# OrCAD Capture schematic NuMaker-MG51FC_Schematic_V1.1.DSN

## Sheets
1 Nu-Link2-Me: size A3; title: Nu-Link2-Me; rev: 1.0; company: CMHuang; note: Nu-Link2-Me
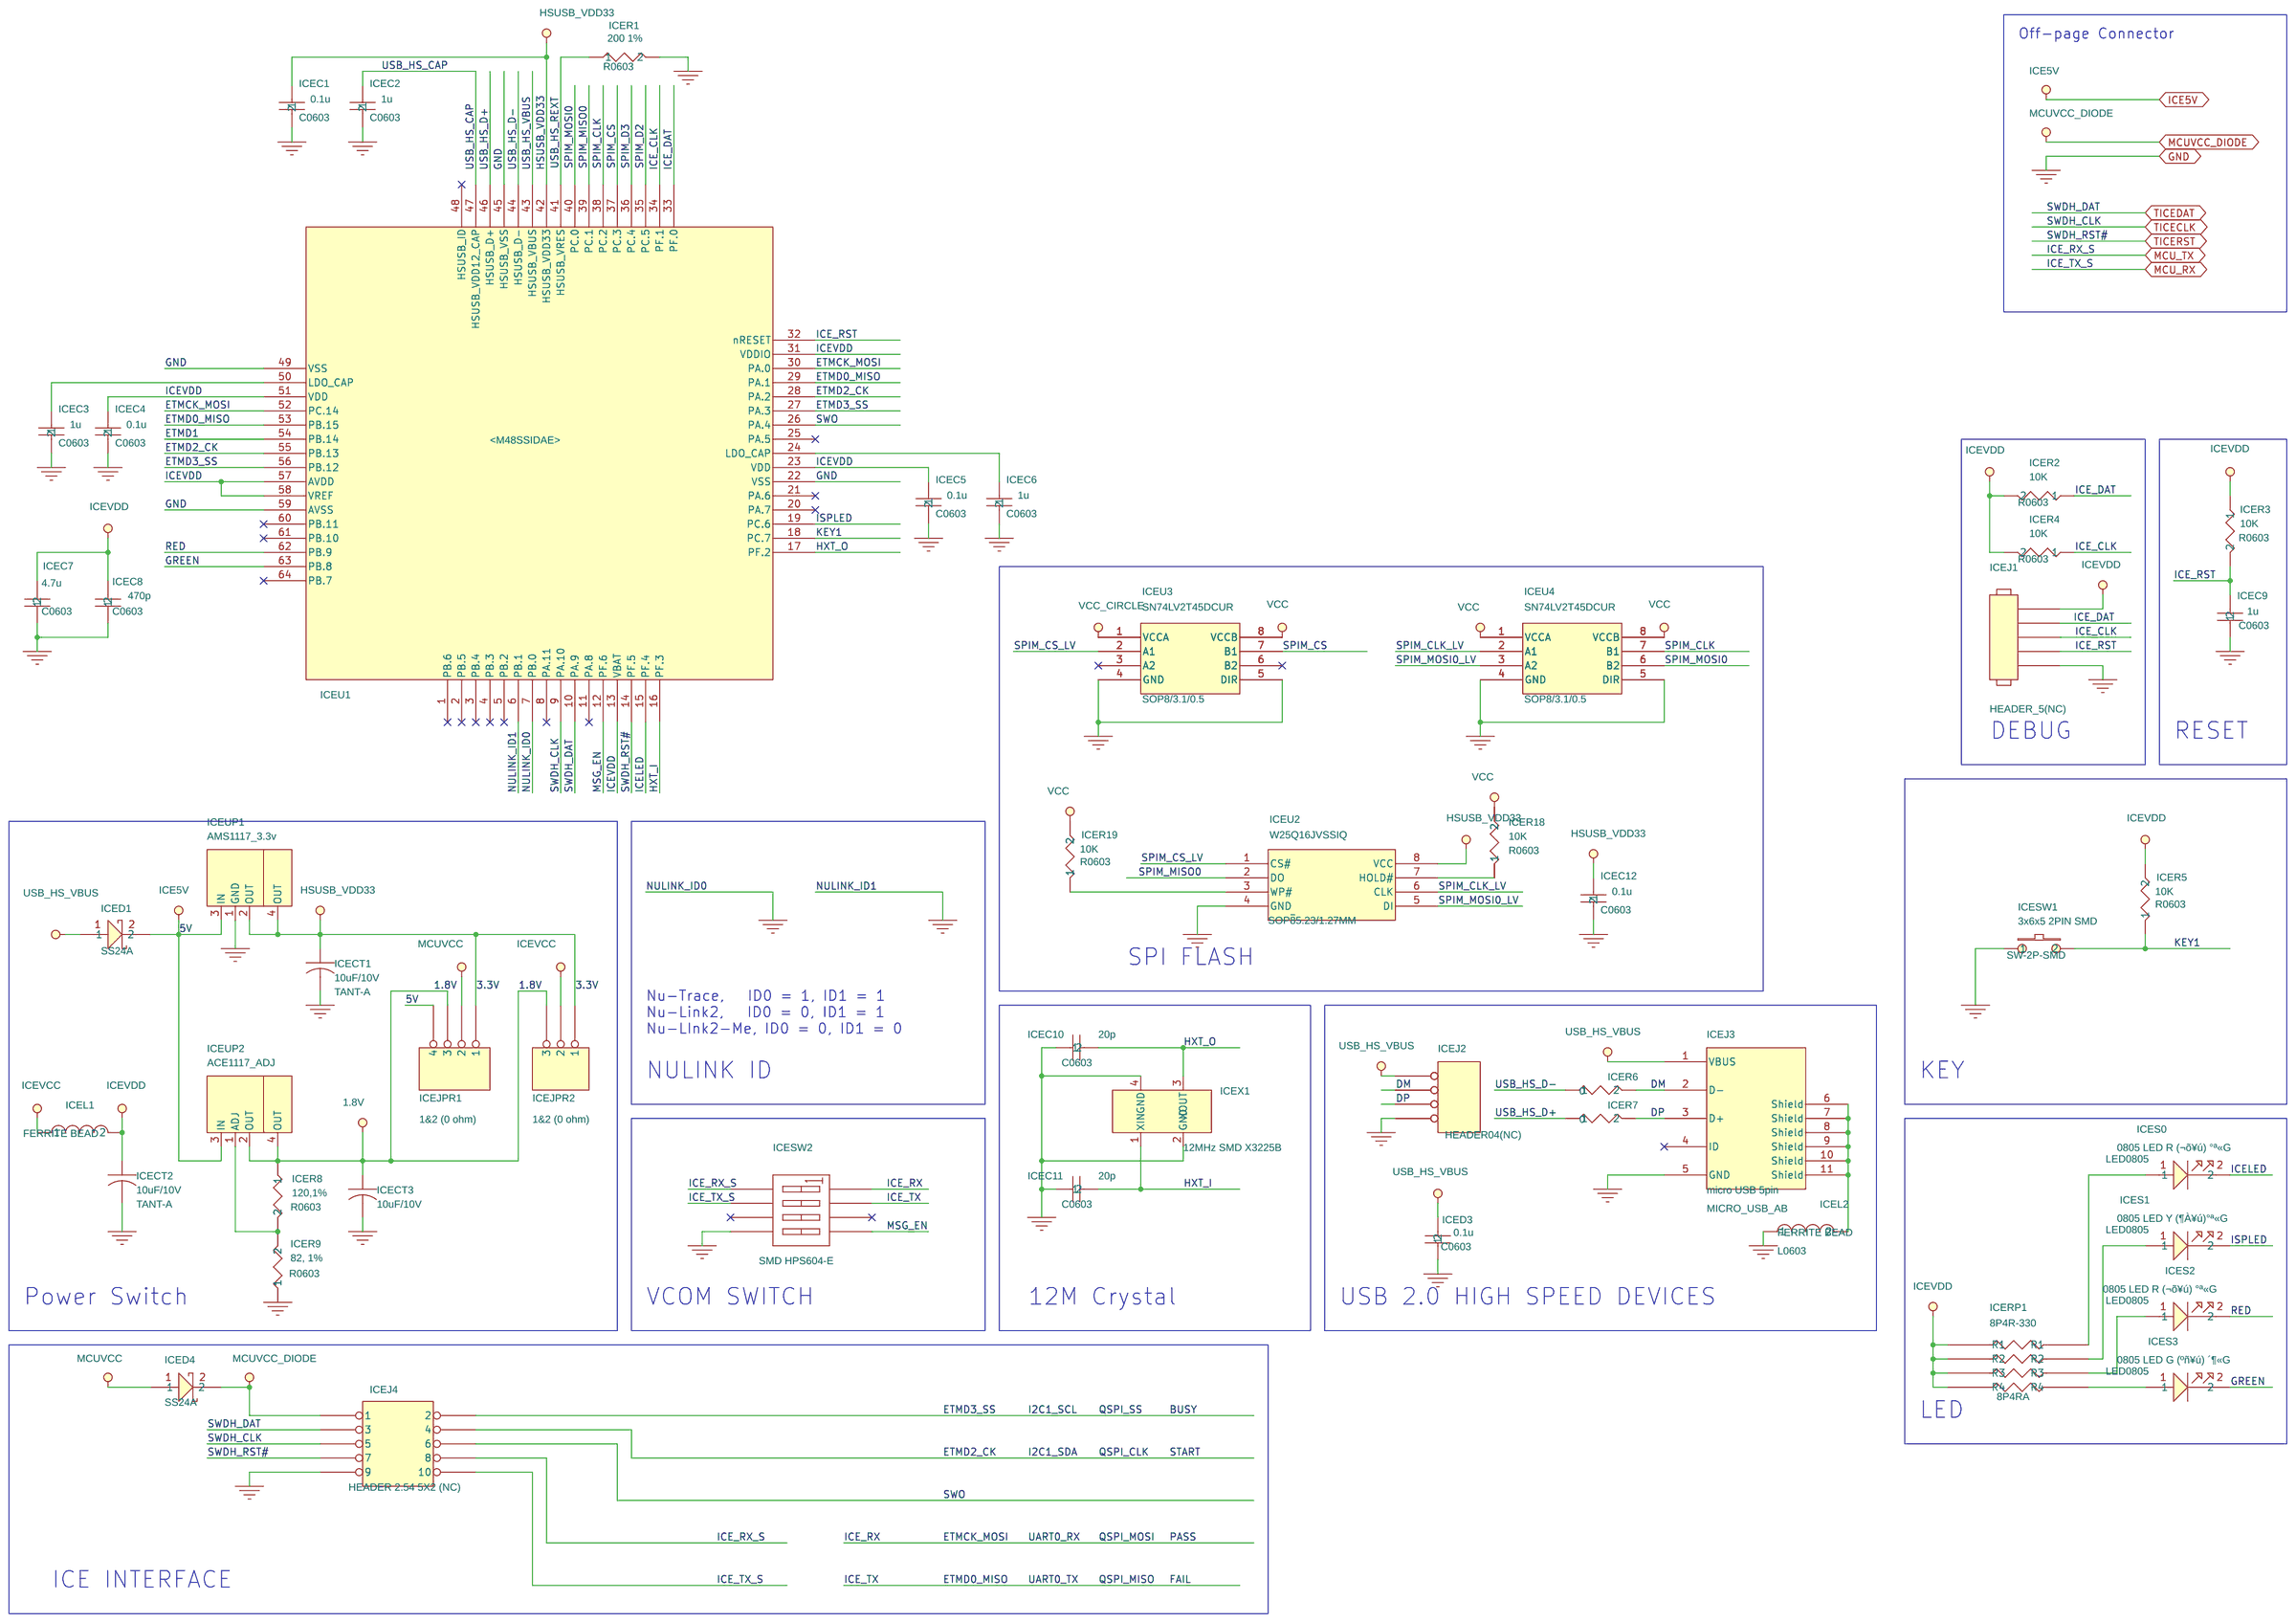
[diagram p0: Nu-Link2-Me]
2 MG51FC9AE: size Custom; title: MS51PC0AE; rev: v1.1; note: NuMaker-MS51PC
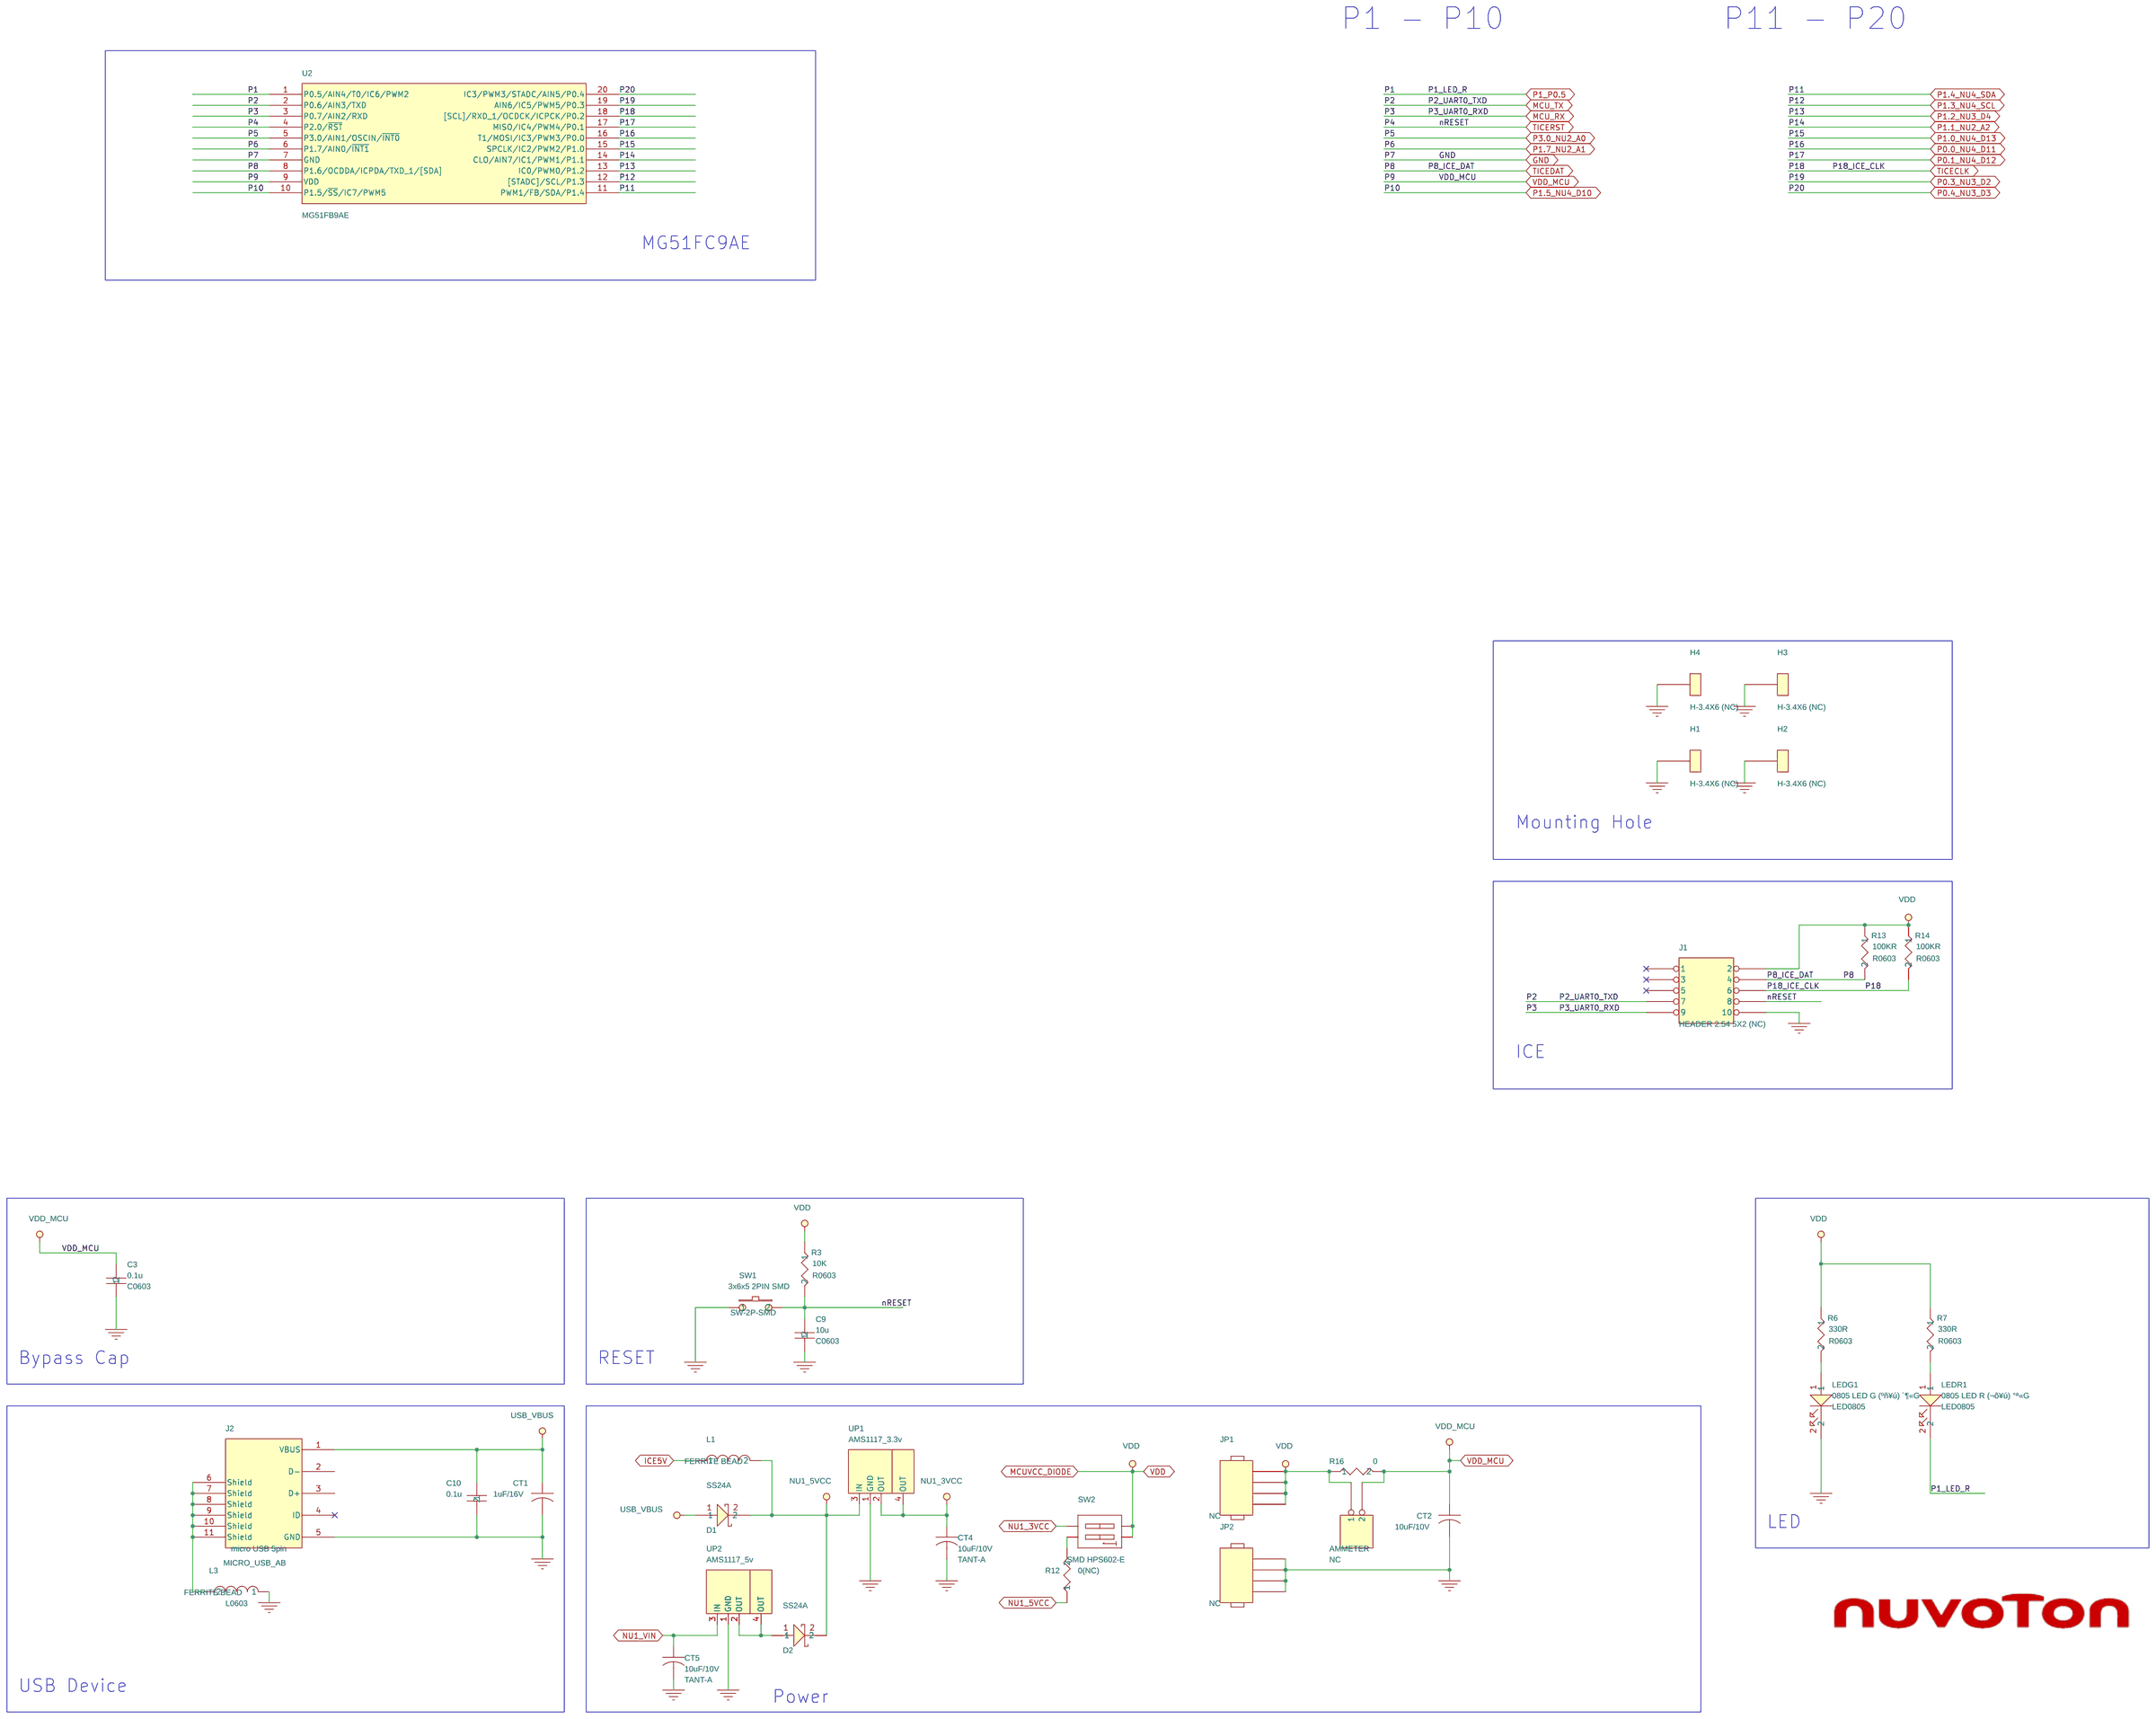
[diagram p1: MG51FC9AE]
3 Ext. Connector: size Custom; title: Ext. Connector; rev: v1.1; note: NuMaker-MS51PC
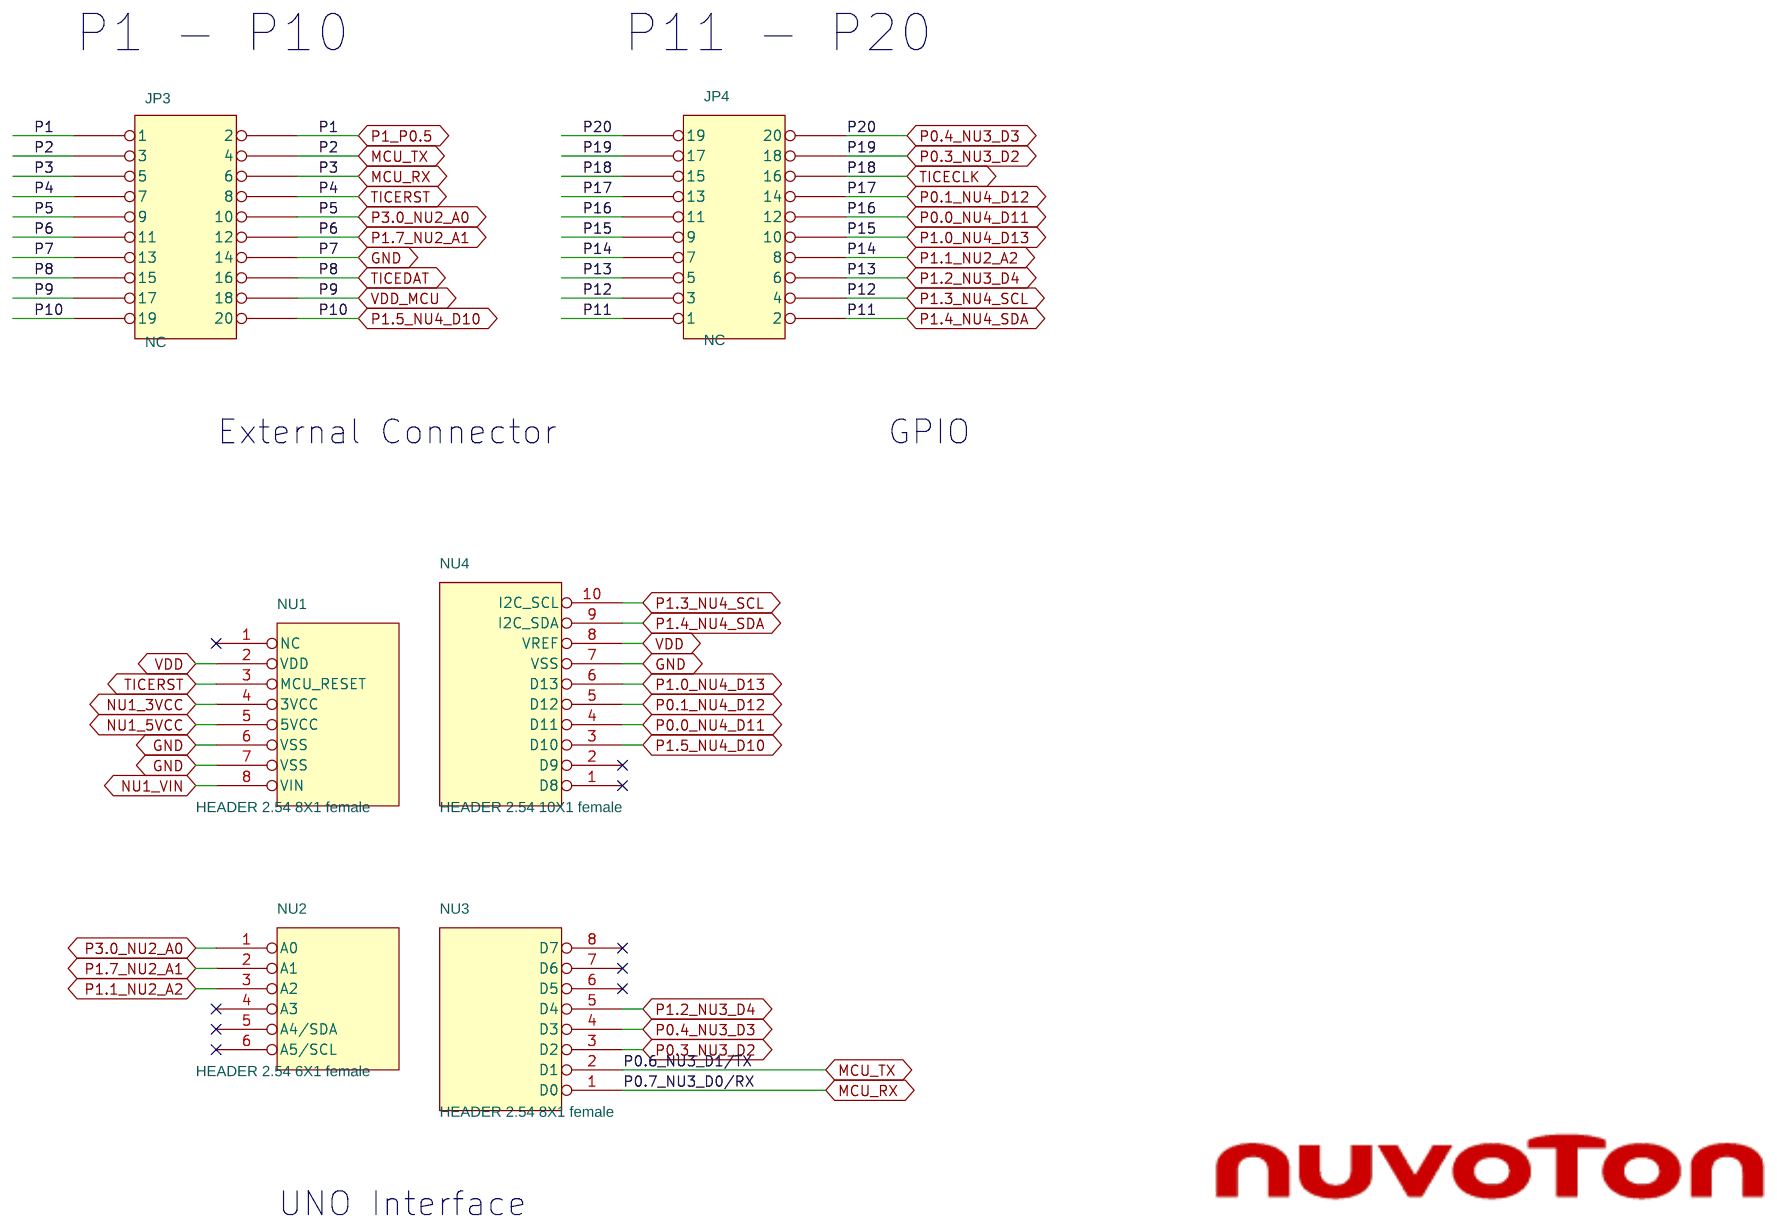
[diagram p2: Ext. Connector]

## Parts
sheet Ext. Connector
JP3  NC  [header10x2]
JP4  NC  [header10x2]
NU1  HEADER 2.54 8X1 female  [SIP-8P]
NU2  HEADER 2.54 6X1 female  [SIP-6P]
NU3  HEADER 2.54 8X1 female  [SIP-8P]
NU4  HEADER 2.54 10X1 female  [SIP-10P]
sheet MG51FC9AE
AMMETER  NC  [HEADER2X1]
C3  0.1u  [C0603]
C9  10u  [C0603]
C10  0.1u  [C0603]
CT1  1uF/16V  [TANT-A]
CT2  10uF/10V  [TANT-A]
CT4  10uF/10V  [TANT-A]
CT5  10uF/10V  [TANT-A]
D1  SS24A  [RB060L]
D2  SS24A  [RB060L]
H1  H-3.4X6 (NC)  [H-3.4X6]
H2  H-3.4X6 (NC)  [H-3.4X6]
H3  H-3.4X6 (NC)  [H-3.4X6]
H4  H-3.4X6 (NC)  [H-3.4X6]
J1  HEADER 2.54 5X2 (NC)  [HEADER5X2]
J2  micro USB 5pin  [MICRO_USB_AB]
JP1  NC  [header1x4]
JP2  NC  [header1x4]
L1  FERRITE BEAD  [L0603]
L3  FERRITE BEAD  [L0603]
LEDG1  0805 LED G (ºñ¥ú) ´¶«G  [LED0805]
LEDR1  0805 LED R (¬õ¥ú) °ª«G  [LED0805]
R3  10K  [R0603]
R6  330R  [R0603]
R7  330R  [R0603]
R12  0(NC)  [R0603]
R13  100KR  [R0603]
R14  100KR  [R0603]
R16  0  [R0603]
SW1  3x6x5 2PIN SMD  [SW-2P-SMD]
SW2  SMD HPS602-E  [SW1X2]
U2  MG51FB9AE  [TSSOP20]
UP1  AMS1117_3.3v  [SOT-223-1]
UP2  AMS1117_5v  [SOT-223-1]
sheet Nu-Link2-Me
ICEC1  0.1u  [C0603]
ICEC2  1u  [C0603]
ICEC3  1u  [C0603]
ICEC4  0.1u  [C0603]
ICEC5  0.1u  [C0603]
ICEC6  1u  [C0603]
ICEC7  4.7u  [C0603]
ICEC8  470p  [C0603]
ICEC9  1u  [C0603]
ICEC10  20p  [C0603]
ICEC11  20p  [C0603]
ICEC12  0.1u  [C0603]
ICECT1  10uF/10V  [TANT-A]
ICECT2  10uF/10V  [TANT-A]
ICECT3  10uF/10V  [TANT-A]
ICED1  SS24A  [RB060L]
ICED3  0.1u  [C0603]
ICED4  SS24A  [RB060L]
ICEJ1  HEADER_5(NC)  [HEADER5X1]
ICEJ2  HEADER04(NC)  [HEADER04]
ICEJ3  micro USB 5pin  [MICRO_USB_AB]
ICEJ4  HEADER 2.54 5X2 (NC)  [HEADER5X2]
ICEJPR1  1&2 (0 ohm)  [R0603X3]
ICEJPR2  1&2 (0 ohm)  [R0603X2]
ICEL1  FERRITE BEAD  [L0603]
ICEL2  FERRITE BEAD  [L0603]
ICER1  200 1%  [R0603]
ICER2  10K  [R0603]
ICER3  10K  [R0603]
ICER4  10K  [R0603]
ICER5  10K  [R0603]
ICER6  0  [R0603]
ICER7  0  [R0603]
ICER8  120,1%  [R0603]
ICER9  82, 1%  [R0603]
ICER18  10K  [R0603]
ICER19  10K  [R0603]
ICERP1  8P4R-330  [8P4RA]
ICES0  0805 LED R (¬õ¥ú) °ª«G  [LED0805]
ICES1  0805 LED Y (¶À¥ú)°ª«G  [LED0805]
ICES2  0805 LED R (¬õ¥ú) °ª«G  [LED0805]
ICES3  0805 LED G (ºñ¥ú) ´¶«G  [LED0805]
ICESW1  3x6x5 2PIN SMD  [SW-2P-SMD]
ICESW2  SMD HPS604-E  [SW1X4]
ICEU1  M48SSIDAE  [LQFP64_7x7_M48SSIDAE]
ICEU2  W25Q16JVSSIQ  [SOP8\5.23/1.27MM]
ICEU3  SN74LV2T45DCUR  [SOP8/3.1/0.5]
ICEU4  SN74LV2T45DCUR  [SOP8/3.1/0.5]
ICEUP1  AMS1117_3.3v  [SOT-223-1]
ICEUP2  ACE1117_ADJ  [SOT-223-1]
ICEX1  12MHz SMD X3225B  [CRYSTAL_SMD]

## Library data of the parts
JP3 = HEADER_10X2
JP4 = HEADER_10X2_1
NU1 = POWER_CONNECT_0
NU2 = ADC_CONNECT_0
NU3 = PWM0_CONNECT_0
NU4 = PWM1_CONNECT_1
AMMETER = HEADER_2
C3 = CAP-C: Package: 0603; element_no: C0004
C9 = CAP-C_1: Package: 0603; element_no: C0006
C10 = C_0.1u: element_no: C0004
CT1 = C_1uF_16V
CT2 CT4 CT5 ICECT1-ICECT3 = C_10uF_10V
D1 ICED1 = D_SS24A
D2 ICED4 = D_SS24A_1
H1-H4 = TEST_POINT
ICEJ4 J1 = HEADER_5X2
ICEJ3 J2 = micro_USB_5pin_0
JP1 JP2 = HEADER_4
ICEL2 L1 = FERRITE_BEAD_1
ICEL1 L3 = FERRITE_BEAD
ICES2 LEDG1 = LED_0_1: Package: KP-2012; Vendor: Kingbright
ICES1 LEDR1 = LED_0: Package: KP-2012; Vendor: Kingbright
ICER19 R3 = R_0_1: Package: 0603
ICER1 R6 = R_0_4: Package: 0603
ICER5 R7 = R_0: Package: 0603
R12 = R_0_3
ICER2 R13 = R_0_2: Package: 0603
ICER3 R14 = R_0_5: Package: 0603
R16 = R_0_6
ICESW1 SW1 = SW_PUSHBUTTON_0
SW2 = SW_DIP-4_2
U2 = SA8191_LQFP_48L_2
ICEUP1 UP1 UP2 = TO-247_Regulator_10
ICEC1 = CAP-C_9: Package: 0603; element_no: C0004
ICEC2 = CAP-C_10: Package: 0603; element_no: C0006
ICEC3 = CAP-C_12: Package: 0603; element_no: C0006
ICEC4 = CAP-C_2: Package: 0603; element_no: C0004
ICEC5 = CAP-C_5: Package: 0603; element_no: C0004
ICEC6 = CAP-C_4: Package: 0603; element_no: C0006
ICEC7 = CAP-C: Package: 0603
ICEC8 = CAP-C_7: Package: 0603
ICEC9 = CAP-C_6: Package: 0603; element_no: C0006
ICEC10 = CAP-C_3: Package: 0603
ICEC11 = CAP-C_11: Package: 0603
ICEC12 = CAP-C_8: Package: 0603; element_no: C0004
ICED3 = CAP-C_1: Package: 0603; element_no: C0004
ICEJ1 = HEADER_5_v2
ICEJ2 = HEADER_4_v2
ICEJPR1 = HEADER_3_0
ICEJPR2 = HEADER_3
ICER4 = R_0_7: Package: 0603
ICER6 = R_33
ICER7 = R_33_1
ICER8 = R_0_3: Package: 0603
ICER9 = R_0_8: Package: 0603
ICER18 = R_0_6: Package: 0603
ICERP1 = R-PACK8_0
ICES0 = LED_0_3: Package: KP-2012; Vendor: Kingbright
ICES3 = LED_0_2: Package: KP-2012; Vendor: Kingbright
ICESW2 = SW_DIP-4_SM
ICEU1 = M487SIDAE_0: M487SIDAE: <M48SSIDAE>
ICEU2 = W25P10_20_40_SOIC_0: Package: SOP8; Vendor: WINBOND
ICEU3 ICEU4 = SN74LV2T45
ICEUP2 = TO-247_Regulator_0
ICEX1 = Crystal_SMD_1

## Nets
1.8V: ICECT3.1 ICEJPR1.3 ICEJPR2.3 ICER8.1 ICEUP2.2(OUT) ICEUP2.4(OUT)
3.3V: ICEC1.1 ICEC12.1 ICECT1.1 ICEJPR1.1 ICEJPR2.1 ICER18.2 ICER19.2 ICEU1.42(HSUSB_VDD33) ICEU2.8(VCC) ICEU3.1(VCCA) ICEU4.1(VCCA) ICEUP1.2(OUT) ICEUP1.4(OUT)
GND: C3.1 C9.1 C10.2 CT1.2 CT2.2 CT4.2 CT5.2 H1.1 H2.1 H3.1 H4.1 ICEC1.2 ICEC2.2 ICEC3.2 ICEC4.2 ICEC5.2 ICEC6.2 ICEC7.1 ICEC8.1 ICEC9.1 ICEC10.1 ICEC11.1 ICEC12.2 ICECT1.2 ICECT2.2 ICECT3.2 ICED3.1 ICEJ1.5 ICEJ2.4 ICEJ3.5(GND) ICEJ4.9 ICEL2.1 ICER1.2 ICER9.1 ICESW1.1 ICESW2.4(A4) ICEU1.6(PB.1) ICEU1.7(PB.0) ICEU1.22(VSS) ICEU1.45(HSUSB_VSS) ICEU1.49(VSS) ICEU1.59(AVSS) ICEU2.4(GND) ICEU3.4(GND) ICEU3.5(DIR) ICEU4.4(GND) ICEU4.5(DIR) ICEUP1.1(GND) ICEX1.2(GND) ICEX1.4(GND) J1.10 J2.5(GND) JP2.1 JP2.2 JP2.3 JP2.4 JP3.13 JP3.14 L3.1 LEDG1.2 NU1.6(VSS) NU1.7(VSS) NU4.7(VSS) SW1.1 U2.7(GND) UP1.1(GND) UP2.1(GND)
VDD: AMMETER.1 ICED4.2 ICEJ4.1 J1.2 JP1.1 JP1.2 JP1.3 JP1.4 NU1.2(VDD) NU4.8(VREF) R3.1 R6.1 R7.1 R13.1 R14.1 R16.1 SW2.3(B1) SW2.4(B2)
VDD_MCU: AMMETER.2 C3.2 CT2.1 JP3.17 JP3.18 R16.2 U2.9(VDD)
BUSY: ICEJ4.2 ICEU1.27(PA.3) ICEU1.56(PB.12)
DM: ICEJ2.2 ICEJ3.2(D-) ICER6.2
DP: ICEJ2.3 ICEJ3.3(D+) ICER7.2
ETMD1: ICEU1.54(PB.14)
ETMD2_CK: ICEJ4.4 ICEU1.28(PA.2) ICEU1.55(PB.13)
GREEN: ICES3.2 ICEU1.63(PB.8)
HXT_I: ICEC11.2 ICEU1.16(PF.3) ICEX1.1(XIN)
HXT_O: ICEC10.2 ICEU1.17(PF.2) ICEX1.3(XOUT)
ICE5V: ICED1.2 ICEJPR1.4 ICEUP1.3(IN) ICEUP2.3(IN) L1.1
ICE_CLK: ICEJ1.3 ICER4.1 ICEU1.34(PF.1)
ICE_DAT: ICEJ1.2 ICER2.1 ICEU1.33(PF.0)
ICE_RST: ICEC9.2 ICEJ1.4 ICER3.2 ICEU1.32(nRESET)
ICE_RX: ICESW2.8(B1) ICEU1.30(PA.0) ICEU1.52(PC.14)
ICE_TX: ICESW2.7(B2) ICEU1.29(PA.1) ICEU1.53(PB.15)
ICELED: ICES0.2 ICEU1.15(PF.4)
ICEVCC: ICEJPR2.2 ICEL1.1
ICEVDD: ICEC4.1 ICEC5.1 ICEC7.2 ICEC8.2 ICECT2.1 ICEJ1.1 ICEL1.2 ICER2.2 ICER3.1 ICER4.2 ICER5.2 ICERP1.1(R1) ICERP1.3(R2) ICERP1.5(R3) ICERP1.7(R4) ICEU1.13(VBAT) ICEU1.23(VDD) ICEU1.31(VDDIO) ICEU1.51(VDD) ICEU1.57(AVDD) ICEU1.58(VREF) ICEU3.8(VCCB) ICEU4.8(VCCB)
ISPLED: ICES1.2 ICEU1.19(PC.6)
KEY1: ICER5.1 ICESW1.2 ICEU1.18(PC.7)
MCU_RX: ICEJ4.10 ICESW2.2(A2) J1.9 JP3.5 JP3.6 NU3.1(D0) U2.3(P0.7/AIN2/RXD)
MCU_TX: ICEJ4.8 ICESW2.1(A1) J1.7 JP3.3 JP3.4 NU3.2(D1) U2.2(P0.6/AIN3/TXD)
MCUVCC: ICED4.1 ICEJPR1.2
MSG_EN: ICESW2.5(B4) ICEU1.12(PF.6)
NU1_3VCC: CT4.1 NU1.4(3VCC) SW2.2(A2) UP1.2(OUT) UP1.4(OUT)
NU1_5VCC: D1.2 D2.2 L1.2 NU1.5(5VCC) R12.1 UP1.3(IN)
NU1_VIN: CT5.1 NU1.8(VIN) UP2.3(IN)
P0.0_NU4_D11: JP4.11 JP4.12 NU4.4(D11) U2.16(T1/MOSI/IC3/PWM3/P0.0)
P0.1_NU4_D12: JP4.13 JP4.14 NU4.5(D12) U2.17(MISO/IC4/PWM4/P0.1)
P0.3_NU3_D2: JP4.17 JP4.18 NU3.3(D2) U2.19(AIN6/IC5/PWM5/P0.3)
P0.4_NU3_D3: JP4.19 JP4.20 NU3.4(D3) U2.20(IC3/PWM3/STADC/AIN5/P0.4)
P1.0_NU4_D13: JP4.9 JP4.10 NU4.6(D13) U2.15(SPCLK/IC2/PWM2/P1.0)
P1.1_NU2_A2: JP4.7 JP4.8 NU2.3(A2) U2.14(CLO/AIN7/IC1/PWM1/P1.1)
P1.2_NU3_D4: JP4.5 JP4.6 NU3.5(D4) U2.13(IC0/PWM0/P1.2)
P1.3_NU4_SCL: JP4.3 JP4.4 NU4.10(I2C_SCL) U2.12([STADC]/SCL/P1.3)
P1.4_NU4_SDA: JP4.1 JP4.2 NU4.9(I2C_SDA) U2.11(PWM1/FB/SDA/P1.4)
P1.5_NU4_D10: JP3.19 JP3.20 NU4.3(D10) U2.10(P1.5/~{SS}/IC7/PWM5)
P1.7_NU2_A1: JP3.11 JP3.12 NU2.2(A1) U2.6(P1.7/AIN0/~{INT1})
P1_P0.5: JP3.1 JP3.2 LEDR1.2 U2.1(P0.5/AIN4/T0/IC6/PWM2)
P3.0_NU2_A0: JP3.9 JP3.10 NU2.1(A0) U2.5(P3.0/AIN1/OSCIN/~{INT0})
RED: ICES2.2 ICEU1.62(PB.9)
SPIM_CLK: ICEU1.38(PC.2) ICEU4.7(B1)
SPIM_CLK_LV: ICEU2.6(CLK) ICEU4.2(A1)
SPIM_CS: ICEU1.37(PC.3) ICEU3.7(B1)
SPIM_CS_LV: ICEU2.1(CS#) ICEU3.2(A1)
SPIM_D2: ICEU1.35(PC.5)
SPIM_D3: ICEU1.36(PC.4)
SPIM_MISO0: ICEU1.39(PC.1) ICEU2.2(DO)
SPIM_MOSI0: ICEU1.40(PC.0) ICEU4.6(B2)
SPIM_MOSI0_LV: ICEU2.5(DI) ICEU4.3(A2)
SWO: ICEJ4.6 ICEU1.26(PA.4)
TICECLK: ICEJ4.5 ICEU1.9(PA.10) J1.6 JP4.15 JP4.16 R14.2 U2.18([SCL]/RXD_1/OCDCK/ICPCK/P0.2)
TICEDAT: ICEJ4.3 ICEU1.10(PA.9) J1.4 JP3.15 JP3.16 R13.2 U2.8(P1.6/OCDDA/ICPDA/TXD_1/[SDA])
TICERST: C9.2 ICEJ4.7 ICEU1.14(PF.5) J1.8 JP3.7 JP3.8 NU1.3(MCU_RESET) R3.2 SW1.2 U2.4(P2.0/~{RST})
USB_HS_CAP: ICEC2.1 ICEU1.47(HSUSB_VDD12_CAP)
USB_HS_D+: ICER7.1 ICEU1.46(HSUSB_D+)
USB_HS_D-: ICER6.1 ICEU1.44(HSUSB_D-)
USB_HS_REXT: ICER1.1 ICEU1.41(HSUSB_VRES)
USB_HS_VBUS: ICED1.1 ICED3.2 ICEJ2.1 ICEJ3.1(VBUS) ICEU1.43(HSUSB_VBUS)
USB_VBUS: C10.1 CT1.1 D1.1 J2.1(VBUS)
N16825237: LEDG1.1 R6.2
N16825240: LEDR1.1 R7.2
N16840819: ICEC6.1 ICEU1.24(LDO_CAP)
N16840960: ICEC3.1 ICEU1.50(LDO_CAP)
N17019924: ICER8.2 ICER9.2 ICEUP2.1(ADJ)
N17029977: ICERP1.8(R4) ICES3.1
N17029979: ICERP1.6(R3) ICES2.1
N17030004: ICERP1.4(R2) ICES1.1
N17030010: ICERP1.2(R1) ICES0.1
N17042369: ICEJ3.6(Shield) ICEJ3.7(Shield) ICEJ3.8(Shield) ICEJ3.9(Shield) ICEJ3.10(Shield) ICEJ3.11(Shield) ICEL2.2
N17110356: J2.6(Shield) J2.7(Shield) J2.8(Shield) J2.9(Shield) J2.10(Shield) J2.11(Shield) L3.2
N17125028: R12.2 SW2.1(A1)
N17155328: ICER18.1 ICEU2.7(HOLD#)
N17155343: ICER19.1 ICEU2.3(WP#)
N17167442: D2.1 UP2.2(OUT) UP2.4(OUT)

Not connected (* = marked no-connect by the designer): ICEJ3 4(ID)*; ICESW2 3(A3)* 6(B3)*; ICEU1 1(PB.6)* 2(PB.5)* 3(PB.4)* 4(PB.3)* 5(PB.2)* 8(PA.11)* 11(PA.8)* 20(PA.7)* 21(PA.6)* 25(PA.5)* 48(HSUSB_ID)* 60(PB.11)* 61(PB.10)* 64(PB.7)*; ICEU3 3(A2)* 6(B2)*; J1 1* 3* 5*; J2 2(D-) 3(D+) 4(ID)*; NU1 1(NC)*; NU2 4(A3)* 5(A4/SDA)* 6(A5/SCL)*; NU3 6(D5)* 7(D6)* 8(D7)*; NU4 1(D8)* 2(D9)*

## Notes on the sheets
sheet 1
- Off-page Connector
- DEBUG
- RESET
- SPI FLASH
- Nu-Trace,   ID0 = 1, ID1 = 1
  Nu-Link2,   ID0 = 0, ID1 = 1
  Nu-LInk2-Me, ID0 = 0, ID1 = 0
- NULINK ID
- KEY
- Power Switch
- VCOM SWITCH
- 12M Crystal
- USB 2.0 HIGH SPEED DEVICES
- LED
- ICE INTERFACE
sheet 2
- P1 - P10
- P11 - P20
- MG51FC9AE
- Mounting Hole
- ICE
- Bypass Cap
- RESET
- LED
- USB Device
- Power
sheet 3
- P1 - P10
- P11 - P20
- External Connector
- GPIO
- UNO Interface
